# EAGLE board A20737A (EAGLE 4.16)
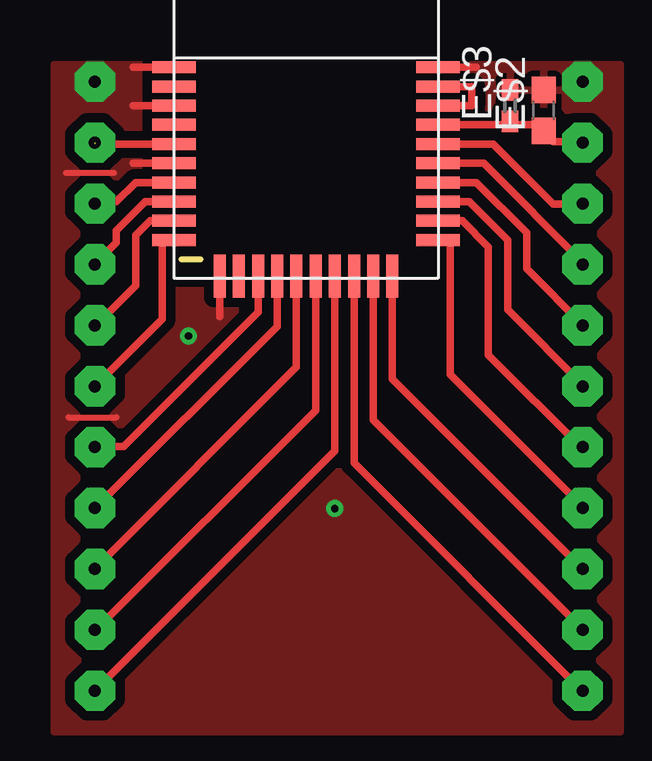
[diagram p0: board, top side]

Size 0.8 x 0 mm. Coordinates in mm from the lower left corner, seen from the top.
Outline: 0,0 0.8,0
Copper layers (1*16): Top 0.035mm / dielectric 1.5mm / Bottom 0.035mm
Design rules "default": minimum track width 10mil, minimum drill 24mil, track to track 8mil, track to pad 8mil, pad to pad 8mil, via to via 8mil, smd to smd 8mil, copper to edge 40mil, drill to drill 8mil, minimum pad ring 10mil, minimum via ring 8mil, stop-mask expansion 4mil, vias tented up to drill 0mil, thermal gap 10mil

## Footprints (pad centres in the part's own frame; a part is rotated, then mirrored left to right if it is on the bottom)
A20737A = smd 1.8 x 0.5: P$1 -5.5,8.4; P$2 -5.5,7.6; P$3 -5.5,6.8; P$4 -5.5,6; P$5 -5.5,5.2; P$6 -5.5,4.4; P$7 -5.5,3.6; P$8 -5.5,2.8; P$9 -5.5,2; P$10 -5.5,1.2; P$21 5.5,1.2; P$22 5.5,2; P$23 5.5,2.8; P$24 5.5,3.6; P$25 5.5,4.4; P$26 5.5,5.2; P$27 5.5,6; P$28 5.5,6.8; P$29 5.5,7.6; P$30 5.5,8.4 | smd 0.5 x 1.8: P$11 -3.6,-0.3; P$12 -2.8,-0.3; P$13 -2,-0.3; P$14 -1.2,-0.3; P$15 -0.4,-0.3; P$16 0.4,-0.3; P$17 1.2,-0.3; P$18 2,-0.3; P$19 2.8,-0.3; P$20 3.6,-0.3
C0603 = smd 1.1 x 1: 1 -0.85,0; 2 0.85,0
C0402 = smd 0.9 x 0.7: 1 -0.65,0; 2 0.65,0

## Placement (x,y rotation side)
E$1  [A20737A]  5.2,-0.4 0 top
E$2  [C0603]  not placed on the board
E$3  [C0402]  not placed on the board

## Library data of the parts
E$1 = anaren
E$2 E$3 = ref-packages

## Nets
GND: E$2.2 E$3.2

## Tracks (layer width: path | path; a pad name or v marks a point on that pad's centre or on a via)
GND  (via drill 0.3, 0.5 pad 1.68)
  Top 0.254: -4.8,3.6 -2.8,3.6 | -4.7,-6.6 -2.7,-6.6
  Top 0.305: -2,8 0,8 | -2,6.4 0.4,6.4 | 10.4,8 12.3,8 | -2,4 -0.4,4 | 1.6,-2.4 1.6,-0.8
  other vias: -3.6,7.4 16.72,7.4 0.3,-3.2 6.4,-10.4
  pour Top (isolate 0.406): -5.3,-19.7 -5.3,8.1 18.3,8.1 18.3,-19.7
S$2  (via drill 0.5 pad 1.68)
  other vias: -3.6,-10.38
S$3  (via drill 0.5 pad 1.68)
  other vias: 16.72,-0.22
S$4  (via drill 0.5 pad 1.68)
  other vias: 16.72,-18
S$5  (via drill 0.5 pad 1.68)
  other vias: -3.6,-12.92
S$7
  Top 0.305: 10.4,4.8 13,4.8 15.5,2.3 16.7,2.3
S$8  (via drill 0.5 pad 1.68)
  other vias: 16.72,2.32
S$9
  Top 0.305: 10.4,6.4 12.1,6.4 12.1,7.2 10.4,7.2
S$10  (via drill 0.5 pad 1.68)
  other vias: 16.72,-15.46
S$11  (via drill 0.5 pad 1.68)
  other vias: 16.72,4.86
S$12
  Top 0.305: 4.8,-0.8 4.8,-4.5 -3.5,-12.8
S$13  (via drill 0.5 pad 1.68)
  other vias: 16.72,-12.92
S$14  (via drill 0.5 pad 1.68)
  other vias: 16.72,-10.38
S$16
  Top 0.305: 6.4,-0.4 6.4,-8 -3.6,-18
S$17  (via drill 0.5 pad 1.68)
  other vias: 16.72,-7.84
S$18
  Top 0.305: 5.6,-0.8 5.6,-6.3 -3.6,-15.5
S$19
  Top 0.305: -3.4,2.4 -2.7,2.4 -1.9,3.2 0,3.2
S$20  (via drill 0.5 pad 1.68)
  other vias: 16.72,-2.76
S$21
  Top 0.305: 16.8,-0.2 12.6,4 10,4
S$22  (via drill 0.5 pad 1.68)
  other vias: 16.72,-5.3
S$23
  Top 0.305: -3.6,0 -3.6,-0.2 -2.7,0.7 -2.7,1.2 -1.5,2.4 0,2.4
S$24
  Top 0.305: -3.6,-2.8 -1.9,-1.1 -1.9,1 -1.3,1.6 0,1.6
S$25
  Top 0.305: -0.8,0.8 -0.8,-2.5 -3.6,-5.3
S$26  (via drill 0.5 pad 1.68)
  other vias: -3.6,2.32
S$27  (via drill 0.5 pad 1.68)
  other vias: -3.6,-15.46
S$28  (via drill 0.5 pad 1.68)
  other vias: -3.6,-0.22
S$29  (via drill 0.5 pad 1.68)
  other vias: -3.6,-18
S$30
  Top 0.305: 4,-0.8 4,-2.8 -3.6,-10.4
S$31
  Top 0.305: -3.5,-7.8 -2.4,-7.8 3.2,-2.2 3.2,-0.8
S$32  (via drill 0.5 pad 1.68)
  other vias: -3.6,-7.84
S$33
  Top 0.305: 10,5.6 14.8,5.6 15.5,4.9 16.7,4.9
S$34  (via drill 0.5 pad 1.68)
  other vias: -3.6,-2.76
S$35
  Top 0.305: 10,3.2 12.3,3.2 14.4,1.1 14.4,-0.4 16.8,-2.8
S$36
  Top 0.305: 8,-0.4 8,-6.7 16.8,-15.5
S$37  (via drill 0.5 pad 1.68)
  other vias: -3.6,-5.3
S$38
  Top 0.305: 8.8,-0.4 8.8,-5 16.8,-13
S$39  (via drill 0.5 pad 1.68)  (1 unrouted)
  Top 0.305: -3.6,4.8 0,4.8
  other vias: -3.6,4.86
S$40
  Top 0.305: 7.2,-0.4 7.2,-8.5 16.8,-18.1
S$47
  Top 0.305: 10.4,2.4 12,2.4 13.6,0.8 13.6,-2.1 16.8,-5.3
S$48
  Top 0.305: 10.4,1.6 11.7,1.6 12.8,0.5 12.8,-4 16.7,-7.9
S$49
  Top 0.305: 10.4,0.8 11.2,0.8 11.2,-4.8 16.8,-10.4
